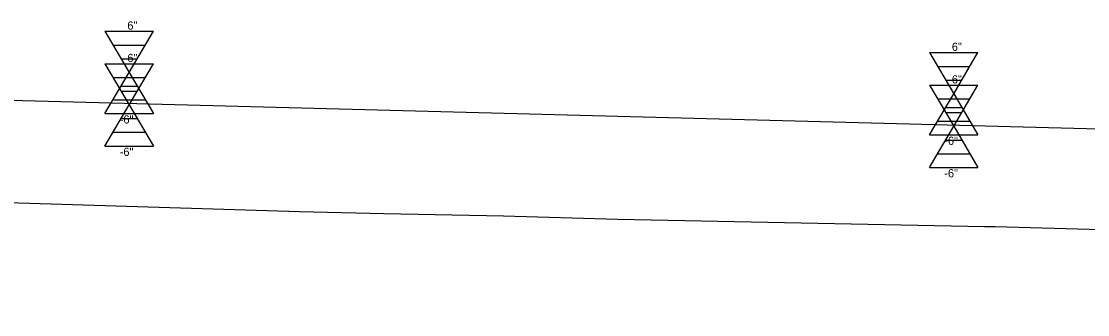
# Model space of a CAD drawing. Extents: x 573468 to 580768, y -57414 to -51768.
# Drawn here: x 574358.7 to 574423.3, y -53061 to -53043.2 of the extents above; entities that cross this region are included whole.
import ezdxf

# ---------------------------------------------------------------- set-up
doc = ezdxf.new("R2010")
doc.units = 0
for name, color, linetype in [('Exist Vertical Profile Ground Line', 7, 'Continuous'), ('Pattern 2', 7, 'Continuous'), ('Prop Vertical Profile Grade', 7, 'Continuous'), ('Scratch_Level_0', 7, 'Continuous')]:
    doc.layers.add(name, color=color, linetype=linetype)

msp = doc.modelspace()

# ---------------------------------------------------------------- linework, layer by layer
at = {"layer": 'Exist Vertical Profile Ground Line'}
msp.add_lwpolyline([(574292.815, -53053.396), (574315.405, -53052.983), (574322.974, -53053.206), (574343.005, -53053.822), (574348.865, -53053.955), (574353.255, -53054.082), (574375.549, -53054.765), (574380.654, -53054.896), (574387.912, -53055.041), (574394.842, -53055.233), (574417.087, -53055.675), (574417.725, -53055.692), (574425.596, -53055.908), (574447.704, -53056.352), (574452.88, -53056.584), (574475.438, -53057.034), (574480.382, -53057.132), (574480.89, -53057.159), (574503.478, -53058.22), (574510.265, -53058.41), (574513.308, -53058.496), (574535.955, -53059.563), (574543.255, -53059.77), (574554.026, -53059.906)], dxfattribs=at)
at = {"layer": 'Pattern 2'}
for p, q in [((574363.748, -53045.794), (574366.68, -53045.794)), ((574363.748, -53045.794), (574365.214, -53048.294)), ((574365.214, -53048.294), (574366.68, -53045.794)), ((574364.236, -53046.628), (574366.191, -53046.628)), ((574413.748, -53047.094), (574416.68, -53047.094)), ((574413.748, -53047.094), (574415.214, -53049.594)), ((574415.214, -53049.594), (574416.68, -53047.094)), ((574364.725, -53047.461), (574365.703, -53047.461)), ((574414.236, -53047.928), (574416.191, -53047.928)), ((574363.748, -53050.794), (574365.214, -53048.294)), ((574365.214, -53048.294), (574366.68, -53050.794)), ((574364.725, -53049.128), (574365.703, -53049.128)), ((574414.725, -53048.761), (574415.703, -53048.761)), ((574364.236, -53049.961), (574366.191, -53049.961)), ((574413.748, -53052.094), (574415.214, -53049.594)), ((574415.214, -53049.594), (574416.68, -53052.094)), ((574414.725, -53050.428), (574415.703, -53050.428)), ((574363.748, -53050.794), (574366.68, -53050.794)), ((574414.236, -53051.261), (574416.191, -53051.261)), ((574413.748, -53052.094), (574416.68, -53052.094))]:
    msp.add_line(p, q, dxfattribs=at)
at = {"layer": 'Prop Vertical Profile Grade'}
msp.add_line((574340.214, -53047.545), (574855.214, -53061.042), dxfattribs=at)
at = {"layer": 'Scratch_Level_0'}
for p, q in [((574363.748, -53043.824), (574366.68, -53043.824)), ((574363.748, -53043.824), (574365.214, -53046.324)), ((574365.214, -53046.324), (574366.68, -53043.824)), ((574364.236, -53044.658), (574366.191, -53044.658)), ((574413.748, -53045.119), (574416.68, -53045.119)), ((574413.748, -53045.119), (574415.214, -53047.619)), ((574415.214, -53047.619), (574416.68, -53045.119)), ((574364.725, -53045.491), (574365.703, -53045.491)), ((574414.236, -53045.953), (574416.191, -53045.953)), ((574363.748, -53048.824), (574365.214, -53046.324)), ((574365.214, -53046.324), (574366.68, -53048.824)), ((574364.725, -53047.158), (574365.703, -53047.158)), ((574414.725, -53046.786), (574415.703, -53046.786)), ((574364.236, -53047.991), (574366.191, -53047.991)), ((574413.748, -53050.119), (574415.214, -53047.619)), ((574415.214, -53047.619), (574416.68, -53050.119)), ((574414.725, -53048.453), (574415.703, -53048.453)), ((574363.748, -53048.824), (574366.68, -53048.824)), ((574414.236, -53049.286), (574416.191, -53049.286)), ((574413.748, -53050.119), (574416.68, -53050.119))]:
    msp.add_line(p, q, dxfattribs=at)

# ---------------------------------------------------------------- texts
at = {"layer": 'Pattern 2'}
for s, p in [('6"', (574365.101, -53045.693)), ('6"', (574415.101, -53046.993)), ('-6"', (574364.64, -53051.397)), ('-6"', (574414.64, -53052.697))]:
    msp.add_text(s, height=0.5, rotation=360, dxfattribs=at).set_placement(p)
at = {"layer": 'Scratch_Level_0'}
for s, p in [('6"', (574365.101, -53043.723)), ('6"', (574415.101, -53045.018)), ('-6"', (574364.64, -53049.427)), ('-6"', (574414.64, -53050.722))]:
    msp.add_text(s, height=0.5, dxfattribs=at).set_placement(p)

doc.saveas('drawing.dxf')
